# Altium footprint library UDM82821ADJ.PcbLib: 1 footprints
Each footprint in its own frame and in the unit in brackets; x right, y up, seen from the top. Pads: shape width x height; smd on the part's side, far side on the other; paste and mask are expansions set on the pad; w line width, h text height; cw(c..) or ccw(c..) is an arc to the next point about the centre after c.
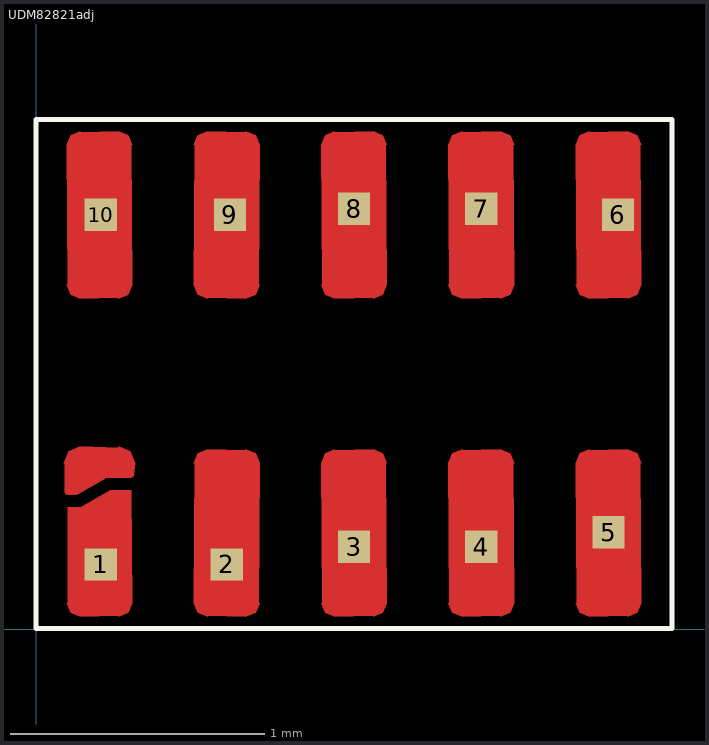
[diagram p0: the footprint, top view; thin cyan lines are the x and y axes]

## UDM82821adj [mil]
pads (10):
  rect 5x5 smd mask+0: 1(10,10) 2(29.5,10) 3(49.18,12.75) 4(68.87,12.75) 5(88.55,15) 6(90,64.06) 7(68.87,65) 8(49.18,65) 9(30,64.06) 10(10,64.06)
Top Layer:
  region: 4.45,21.2 4.58,20.89 4.89,20.76 4.89,20.79 6.25,20.76 6.46,20.84 6.46,20.85 10.92,23.43 14.73,23.39 15.04,23.52 15.17,23.84 15.14,23.84 15.34,25.67 14.58,27.49 12.76,28.25 12.76,28.05 6.86,28.25 5.04,27.49 4.28,25.67 4.48,25.67
  region: 4.89,4.02 4.89,18.84 6.89,18.84 11.45,21.47 14.73,21.47 14.89,4.02 14.27,2.51 12.76,1.89 12.76,2.05 6.86,1.89 5.35,2.51 4.73,4.02
  region: 24.41,4.02 25.04,2.51 26.54,1.89 26.54,2.05 32.45,1.89 33.95,2.51 34.58,4.02 34.42,4.02 34.58,25.67 33.95,27.18 32.45,27.8 32.45,27.64 26.54,27.8 25.04,27.18 24.41,25.67 24.57,25.67
  region: 44.26,4.02 44.1,25.67 44.72,27.18 46.23,27.8 46.23,27.64 52.13,27.8 53.64,27.18 54.26,25.67 54.1,25.67 54.26,4.02 53.64,2.51 52.13,1.89 52.13,2.05 46.23,1.89 44.72,2.51 44.1,4.02
  region: 63.94,4.02 63.78,25.67 64.41,27.18 65.91,27.8 65.91,27.64 71.82,27.8 73.32,27.18 73.95,25.67 73.79,25.67 73.95,4.02 73.32,2.51 71.82,1.89 71.82,2.05 65.91,1.89 64.41,2.51 63.78,4.02
  region: 83.63,4.02 83.47,25.67 84.09,27.18 85.6,27.8 85.6,27.64 91.5,27.8 93.01,27.18 93.63,25.67 93.47,25.67 93.63,4.02 93.01,2.51 91.5,1.89 91.5,2.05 85.6,1.89 84.09,2.51 83.47,4.02
  region: 83.63,53.23 83.47,74.89 84.09,76.39 85.6,77.02 85.6,76.85 91.5,77.02 93.01,76.39 93.63,74.89 93.47,74.89 93.63,53.23 93.01,51.72 91.5,51.1 91.5,51.26 85.6,51.1 84.09,51.72 83.47,53.23
  region: 63.94,53.23 63.78,74.89 64.41,76.39 65.91,77.02 65.91,76.85 71.82,77.02 73.32,76.39 73.95,74.89 73.79,74.89 73.95,53.23 73.32,51.72 71.82,51.1 71.82,51.26 65.91,51.1 64.41,51.72 63.78,53.23
  region: 44.26,53.23 44.1,74.89 44.72,76.39 46.23,77.02 46.23,76.85 52.13,77.02 53.64,76.39 54.26,74.89 54.1,74.89 54.26,53.23 53.64,51.72 52.13,51.1 52.13,51.26 46.23,51.1 44.72,51.72 44.1,53.23
  region: 24.41,53.23 25.04,51.72 26.54,51.1 26.54,51.26 32.45,51.1 33.95,51.72 34.58,53.23 34.42,53.23 34.58,74.89 33.95,76.39 32.45,77.02 32.45,76.85 26.54,77.02 25.04,76.39 24.41,74.89 24.57,74.89
  region: 4.89,53.23 4.73,74.89 5.35,76.39 6.86,77.02 6.86,76.85 12.76,77.02 14.27,76.39 14.89,74.89 14.73,74.89 14.89,53.23 14.27,51.72 12.76,51.1 12.76,51.26 6.86,51.1 5.35,51.72 4.73,53.23
Top Overlay:
  lines w0.79: -0.03,0.08 -0.03,78.82 98.39,78.82 98.39,0.08 -0.03,0.08
Top Paste:
  drawing of 11 lines, arcs and shapes, not listed
Top Solder:
  drawing of 11 lines, arcs and shapes, not listed
3D body: height 47.28, standoff -0.39, extent 0.01,0 98.43,78.74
